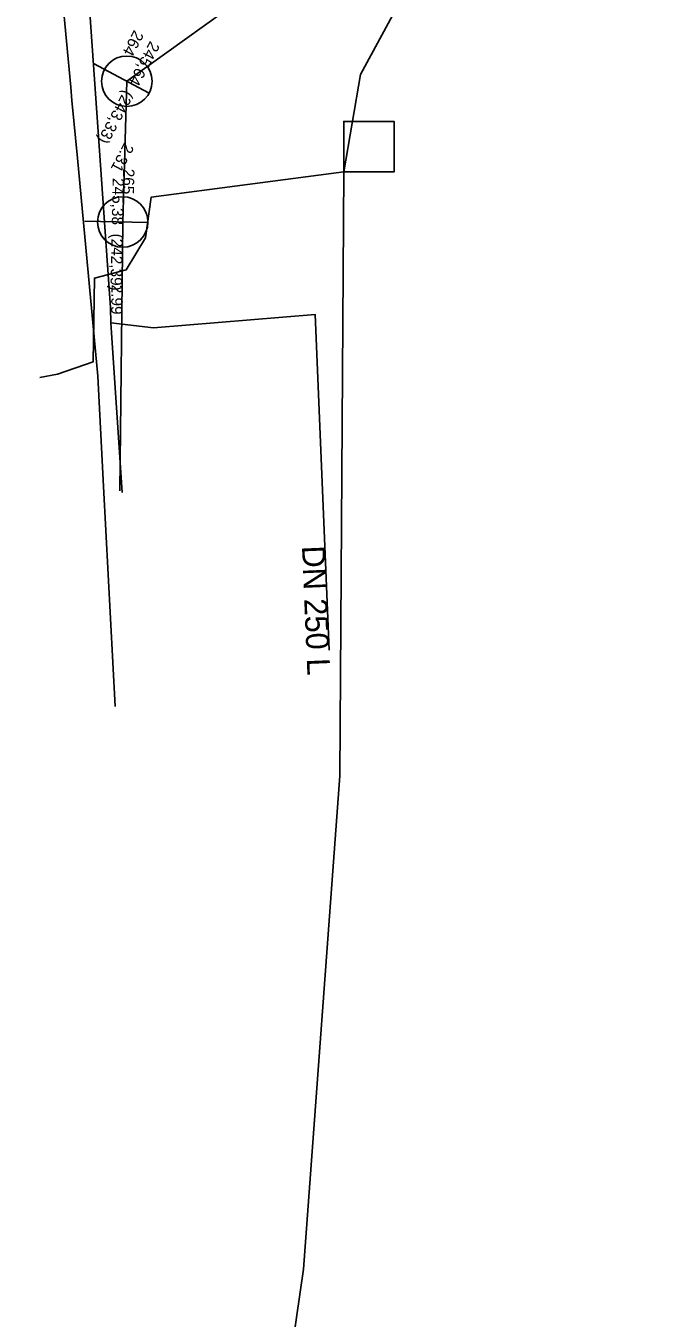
# Model space of a CAD drawing. Extents: x -600636 to -600148, y -1203980 to -1203569.
# Drawn here: x -600603.9 to -600579.1, y -1203856 to -1203804.8 of the extents above; entities that cross this region are included whole.
import ezdxf

# ---------------------------------------------------------------- set-up
doc = ezdxf.new("R2010")
doc.units = 0
for name, color, linetype in [('Cetin kolektor kabelovod', 7, 'Continuous'), ('Cetin nezaměřený', 7, 'Continuous'), ('Cetin zam průběh', 7, 'Continuous'), ('GasNet NTL', 7, 'Continuous'), ('Implicitní', 7, 'Continuous'), ('VaK Břeclav_kanalizace', 7, 'Continuous'), ('VaK Břeclav_kanalizace_popis', 7, 'Continuous'), ('Vak Břeclav_vodovod', 7, 'Continuous'), ('Vak Břeclav_vodovod_popis', 7, 'Continuous')]:
    doc.layers.add(name, color=color, linetype=linetype)

# ---------------------------------------------------------------- blocks, each defined once
blk = doc.blocks.new('MoSymbol 2')
at = {"layer": 'Implicitní'}
blk.add_line((0, 0.0005), (0, -0.00075), dxfattribs=at)
blk.add_circle((0, 0), 0.0005, dxfattribs=at)

msp = doc.modelspace()

# ---------------------------------------------------------------- linework, layer by layer
at = {"layer": 'Cetin kolektor kabelovod'}
msp.add_lwpolyline([(-600591.27, -1203810.59), (-600589.27, -1203810.59), (-600589.27, -1203808.59), (-600591.27, -1203808.59)], close=True, dxfattribs=at)
msp.add_lwpolyline([(-600591.27, -1203810.59), (-600591.42, -1203834.51), (-600592.87, -1203854.05), (-600594.24, -1203863.54), (-600596.19, -1203870.6), (-600600.04, -1203881.6), (-600600.23, -1203882.56), (-600600.33, -1203883.34), (-600600.16, -1203883.94), (-600599.08, -1203885.54), (-600598.54, -1203885.98)], dxfattribs=at)
at = {"layer": 'Cetin nezaměřený'}
msp.add_lwpolyline([(-600600.33, -1203883.34), (-600600.23, -1203882.56), (-600600.04, -1203881.6), (-600596.19, -1203870.6), (-600594.24, -1203863.54), (-600592.87, -1203854.05), (-600591.42, -1203834.51), (-600591.27, -1203810.59)], dxfattribs=at)
at = {"layer": 'Cetin zam průběh'}
for points in [[(-600591.27, -1203810.59), (-600590.6, -1203806.73), (-600588.32, -1203802.51), (-600586.01, -1203800.08), (-600583.97, -1203798.69), (-600581.13, -1203796.91), (-600575.98, -1203796.07), (-600574.075, -1203796.372)], [(-600603.31, -1203818.74), (-600602.61, -1203818.6), (-600601.2, -1203818.11), (-600601.15, -1203814.8), (-600599.89, -1203814.47), (-600599.12, -1203813.2), (-600598.9, -1203811.59), (-600591.27, -1203810.59)]]:
    msp.add_lwpolyline(points, dxfattribs=at)
at = {"layer": 'GasNet NTL'}
msp.add_lwpolyline([(-600589.51, -1203786.96), (-600603.87, -1203790.9), (-600603.51, -1203792.65), (-600602.6, -1203801.75), (-600602.09, -1203807.23), (-600602.04, -1203807.76), (-600601.82, -1203810.05), (-600601.01, -1203818.68), (-600600.79, -1203823.05), (-600600.33, -1203831.768)], dxfattribs=at)
at = {"layer": 'VaK Břeclav_kanalizace'}
for p, q in [((-600583.255, -1203795.061), (-600599.868, -1203807.001)), ((-600599.868, -1203807.001), (-600600.029, -1203812.578)), ((-600600.029, -1203812.578), (-600600.143, -1203823.226))]:
    msp.add_line(p, q, dxfattribs=at)
at = {"layer": 'Vak Břeclav_vodovod'}
msp.add_line((-600600.505, -1203816.572), (-600600.052, -1203823.295), dxfattribs=at)
for points in [[(-600601.355, -1203803.909), (-600600.518, -1203815.976), (-600600.505, -1203816.572)], [(-600591.84, -1203829.536), (-600592.406, -1203816.237), (-600598.806, -1203816.771), (-600600.505, -1203816.572)]]:
    msp.add_lwpolyline(points, dxfattribs=at)

# ---------------------------------------------------------------- block references
at = {"layer": 'VaK Břeclav_kanalizace'}
for p, xscale, yscale, rotation in [((-600599.868, -1203807.001), 1999.750031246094, 1999.7500312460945, -117.97412332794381), ((-600600.029, -1203812.578), 1999.7500312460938, 1999.750031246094, -91.13240440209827)]:
    msp.add_blockref('MoSymbol 2', p, dxfattribs=dict(at, xscale=xscale, yscale=yscale, rotation=rotation))

# ---------------------------------------------------------------- texts
at = {"layer": 'VaK Břeclav_kanalizace_popis'}
for s, height, rotation, p in [('245,64  (243,33)', 0.45494, 242.0259, (-600598.939, -1203805.381)), ('264', 0.4549, 242.0259, (-600599.573, -1203804.946)), ('2.31', 0.4549, 242.0259, (-600599.96, -1203809.404)), ('265', 0.4549, 268.8676, (-600600.017, -1203810.461)), ('245,38  (242,39)', 0.45494, 268.8676, (-600600.428, -1203810.832)), ('2.99', 0.4549, 268.8676, (-600600.47, -1203815.054))]:
    msp.add_text(s, height=height, rotation=rotation, dxfattribs=at).set_placement(p)
at = {"layer": 'Vak Břeclav_vodovod_popis'}
msp.add_text('DN 250 L', height=0.9099, rotation=272.4385, dxfattribs=at).set_placement((-600592.926, -1203825.412))

doc.saveas('drawing.dxf')
